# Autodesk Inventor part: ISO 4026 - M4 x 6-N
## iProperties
Created: 2011-01
Part Number: ISO 4026 - M4 x 6-N
Document SubType Name: Modeling
Designer: eric
Density: 1 g/cm^3
Mass: 0.0631296 g
Surface Area: 1.09453 cm^2
Volume: 0.0631296 cm^3
Author: eric
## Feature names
1. Base1
